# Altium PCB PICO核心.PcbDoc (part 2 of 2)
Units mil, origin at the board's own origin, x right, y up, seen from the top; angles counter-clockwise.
Board outline 3937.01 x 3543.31 mil, 4 copper layers (Top Layer, GND, VCC, Bottom Layer), stack 23.756 mil thick; 147 components, 105 nets, 477 pads, 202 vias.
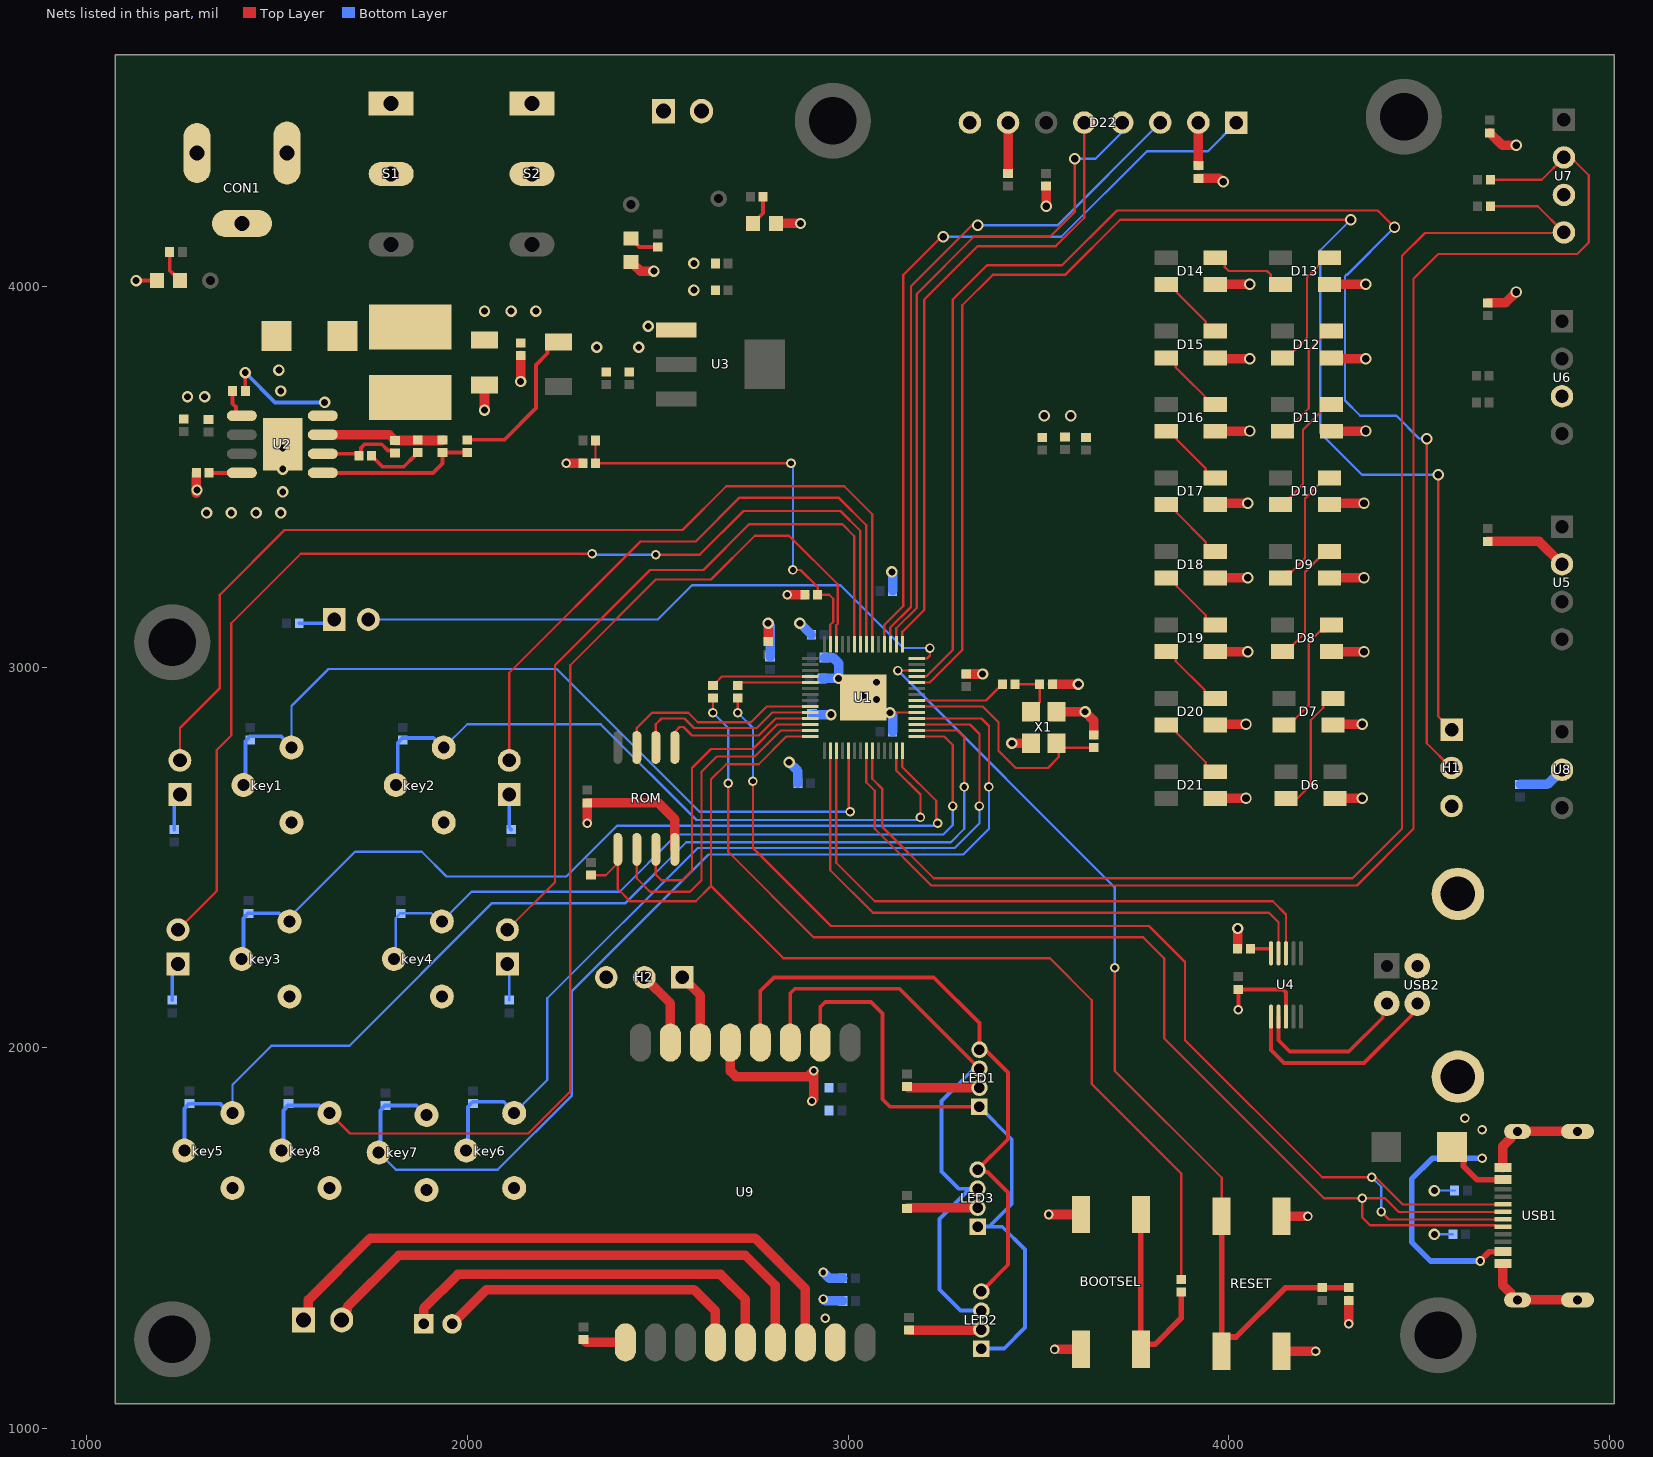
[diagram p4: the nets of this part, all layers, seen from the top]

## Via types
v1: diameter 25, hole 15, Top Layer to Bottom Layer, 71 vias
v2: diameter 30, hole 20, Top Layer to Bottom Layer, 68 vias
v3: diameter 30, hole 18, Top Layer to Bottom Layer, 63 vias

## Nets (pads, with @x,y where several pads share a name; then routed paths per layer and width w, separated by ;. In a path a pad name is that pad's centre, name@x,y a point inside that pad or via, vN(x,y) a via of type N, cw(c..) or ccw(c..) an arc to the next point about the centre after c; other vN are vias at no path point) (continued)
GND: BOOTSEL.1 C2.1 C3.1 C4.1 C5.1 C7.2 C8.1 C9.2 C10.2 C11.1 C12.2 C13.1 C14.1 C15.1 C16.1 C17.1 C18.1 C19.1 C20.1 C21.1 C22.1 C23.1 C24.1 C25.1 C26.1 C27.2 C28.1 C29.2 C30.1 C31.1 C32.1 C33.1 C34.1 C35.1 C36.1 C37.1 C38.1 C39.2 C40.2 C41.2 C42.2 CON1.2 CON1.3 D1.1 D2.2 D3.2 D4.2 D6.3 D7.3 D8.3 D9.3 D10.3 D11.3 D12.3 D13.3 D14.3 D15.3 D16.3 D17.3 D18.3 D19.3 D20.3 D21.3 D22.8 H1.3 H2.3 key1.1 key2.1 key3.1 key4.1 key5.1 key6.1 key7.1 key8.1 P1.2 R2.1 R3.1 R12.1 R13.1 R16.1 R20.2 RESET.2 ROM.4 U1.19 U1.57 U2.7 U2.9 U3.1 U4.3 U5.2 U6.3 U7.3 U8.2 U9.5 U9.16 USB1.1 USB1.12 USB1.13 USB1.14 USB1.15 USB1.16 USB2.0 USB2.4 USB2.5 X1.2 X1.4 | length 5855.8
  Top Layer w6: v3(3110,2880) 3110.63,2880.63 U1.19@3179.76,2880.63
  Top Layer w10: v3(1130,4015) D2.2@1184.37,4015 ; v1(4025,2100) C33.1@4025,2153.27 4141.73,2153.27 4150,2145 U4.3@4150,2081.93
  Top Layer w25: v3@1288.27,3456.73 C7.2@1288.27,3510 ; U2.7@1620.3,3610 1795,3610 C8.1@1810,3595 1933.27,3595 R3.1@1935,3596.73 ; v3(2045,3675) C3.1@2045,3741.34 ; v3(2140,3750) C2.1@2140,3818.27 ; v1(2260,3535) R16.1@2303.27,3535 ; v1(2315,2590) C24.1@2315,2643.27 2501.73,2643.27 2545,2600 ROM.4@2545,2521.14 ; D3.2@2430,4064.37 2430.98,4064.37 2436.79,4058.56 2436.79,4057.58 2454.37,4040 v3(2490,4040) ; U9.5@2690.64,2013.7 2690.64,1939.01 2705.28,1924.37 2894.36,1924.37 v1(2910,1940) 2910,1865 v1(2905,1860) ; C11.1@2790,3066.73 v3(2790,3115) ; D4.2@2810.31,4165 v3(2875,4165) ; v1(2840,3190) C31.1@2886.54,3190 ; C18.1@3310,2981.73 v3(3353.27,2981.73) ; v3(3430,2800) X1.4@3480,2800 ; v2(3520,4210) C35.1@3520,4263.27 ; v1(3527.16,1562.16) BOOTSEL.1@3611.26,1562.16 ; C26.1@3536.73,2955 v3(3605,2955) ; v1(3542.16,1207.84) BOOTSEL.1@3611.26,1207.84 ; X1.2@3546.93,2882.68 v3(3622.32,2882.68) 3645,2860 C25.1@3645,2821.73 ; R20.2@3920,4283.27 3975.38,4283.27 3983.65,4275 v2(3985,4275) ; D21.3@3964.47,2654.92 4044.92,2654.92 v2(4045,2655) ; D20.3@3964.47,2849.92 4044.92,2849.92 v2(4045,2850) ; D19.3@3969.47,3039.92 4049.92,3039.92 v2(4050,3040) ; D18.3@3969.47,3234.92 4049.92,3234.92 v2(4050,3235) ; D17.3@3969.47,3429.92 4049.92,3429.92 v2(4050,3430) ; D16.3@3974.47,3619.92 4054.92,3619.92 v2(4055,3620) ; D15.3@3974.47,3809.92 4054.92,3809.92 v2(4055,3810) ; D14.3@3974.47,4004.92 4054.92,4004.92 v2(4055,4005) ; C29.2@4023.27,2260 v3(4023.27,2313.27) ; RESET.2@4138.74,1202.84 v1(4227.84,1202.84) ; RESET.2@4138.74,1557.16 v1(4207.84,1557.16) ; D6.3@4269.47,2654.92 4349.92,2654.92 v2(4350,2655) ; D7.3@4269.47,2849.92 4349.92,2849.92 v2(4350,2850) ; D8.3@4274.47,3039.92 4354.92,3039.92 v2(4355,3040) ; D9.3@4274.47,3234.92 4354.92,3234.92 v2(4355,3235) ; D10.3@4274.47,3429.92 4354.92,3429.92 v2(4355,3430) ; D11.3@4279.47,3619.92 4359.92,3619.92 v2(4360,3620) ; D12.3@4279.47,3809.92 4359.92,3809.92 v2(4360,3810) ; D13.3@4279.47,4004.92 4359.92,4004.92 v2(4360,4005) ; v1(4315,1275) C27.2@4315,1336.54 ; C36.1@4680,3330 4815,3330 U5.2@4875,3270 ; C34.1@4680,3956.73 4726.73,3956.73 v2(4755,3985) ; C38.1@4685,4403.27 4718.27,4370 v2(4755,4370) ; USB1.1@4720,1433.03 4720,1376.14 4739.89,1356.25 4739.89,1344.39 4746.53,1337.76 USB1.13@4758.39,1337.76 USB1.15@4915.87,1337.76 ; USB1.12@4720,1685 4720,1741.89 4739.89,1761.78 4739.89,1773.64 4746.53,1780.28 USB1.14@4758.39,1780.28 USB1.16@4915.87,1780.28
  Bottom Layer w6: v3(4540,1510) R12.1@4588.27,1510 ; v3(4540,1625) R13.1@4593.27,1625
  Bottom Layer w25: v3(2790,3115) 2790,3113.65 2795,3108.65 C16.1@2795,3026.73 ; v3(2845,2750) 2868.27,2726.73 C12.2@2868.27,2695 ; v3(2873.27,3115) C13.1@2903.27,3085 ; C10.2@2906.73,2875 v3(2955,2875) ; C14.1@2931.73,2970 v3(2975,2970) 2975,3010.36 2960.36,3025 C19.1@2936.73,3025 ; v1(2935,1340) 2939.7,1335.3 2986.24,1335.3 C41.2@2986.54,1335 ; v1(2935,1410) 2949.97,1395.03 C39.2@2985.65,1395.03 ; v3(3110,2880) 3116.73,2873.27 C15.1@3116.73,2830 ; C17.1@3116.73,3200 v3@3116.73,3241.73 ; C9.2@3310,2981.73 v3(3353.27,2981.73) ; C37.1@4765,2691.73 4836.73,2691.73 U8.2@4875,2730
  other v1: 2940,1290
  other v2: 3515,3660 3585,3660
  other v3: 3075,2915 3040,2925 3075,2960 3115,3250 1315,3405 1380,3405 1445,3405 1510,3405 1515,3460 1290,3465 1515,3520 1515,3575 1265,3710 1310,3710 1510,3725 1505,3780 2340,3840 2450,3840 2475,3895 2595,3990 2595,4060
KEY1: key1.2 R27.1 U1.5 | length 2182.4
  Top Layer w6: U1.5@3000.63,2780.24 3001.57,2779.3 3001.57,2625.31 3000.63,2624.37 v1(3005,2620)
  Bottom Layer w6: key1.2@1537.99,2788.43 1537.99,2793.43 1537.99,2897.99 1635,2995 2235,2995 2610,2620 v1(3005,2620)
  Bottom Layer w10: key1.2@1417.01,2695 1417.01,2805.28 1422.2,2810.47 1422.2,2811.46 1429.02,2818.27 1510.64,2818.27 1535.48,2793.43 key1.2@1537.99,2793.43
KEY2: key2.2 R28.1 U1.13 | length 1833.4
  Top Layer w6: U1.13@3126.61,2780.24 3126.61,2728.39 3190,2665 v1(3190,2605)
  Bottom Layer w6: key2.2@1937.99,2788.43 1999.57,2850 2350,2850 2601.5,2598.5 3178.36,2598.5 3184.86,2605 v1(3190,2605)
  Bottom Layer w10: key2.2@1817.01,2690 1817.01,2800.28 1822.2,2805.47 1822.2,2806.46 1829.02,2813.27 1910.64,2813.27 1935.48,2788.43 key2.2@1937.99,2788.43
KEY3: key3.2 R29.1 U1.14 | length 2342.3
  Top Layer w6: U1.14@3142.36,2780.24 3142.36,2737.64 3231.36,2648.64 3231.36,2611.5 3231.36,2593.64 v1(3235,2590)
  Bottom Layer w6: key3.2@1532.99,2331.85 1532.99,2342.99 1705,2515 1880,2515 1945,2450 2260,2450 2393.5,2583.5 3223.36,2583.5 3229.86,2590 v1(3235,2590)
  Bottom Layer w10: key3.2@1412.01,2230 1412.01,2340.28 1417.2,2345.47 1417.2,2346.46 1424.02,2353.27 R29.1@1425,2353.27 1505.64,2353.27 key3.2@1530.02,2328.88
KEY4: key4.2 R30.1 U1.15 | length 2014
  Top Layer w6: U1.15@3179.76,2817.64 3252.36,2817.64 3275,2795 v1(3275,2635)
  Bottom Layer w6: key4.2@1812.01,2230 1812.01,2340.28 1817.2,2345.47 1817.2,2346.46 1824.02,2353.27 R30.1@1825,2353.27 1905.64,2353.27 1930.48,2328.43 key4.2@1937.99,2328.43 ; key4.2@1932.99,2331.85 2011.14,2410 2400,2410 2550,2560 3250,2560 3275,2585 v1(3275,2635)
KEY5: key5.2 R31.1 U1.16 | length 2900.3
  Top Layer w6: U1.16@3179.76,2833.39 3286.61,2833.39 3305,2815 v1(3305,2685)
  Bottom Layer w6: key5.2@1382.99,1828.42 1382.99,1902.99 1485,2005 1690,2005 2065,2380 2415,2380 2575,2540 3270,2540 3305,2575 v1(3305,2685)
  Bottom Layer w10: key5.2@1257.01,1730 1257.01,1840.28 1262.2,1845.47 1262.2,1846.46 1269.02,1853.27 R31.1@1270,1853.27 1350.64,1853.27 1375.48,1828.42 key5.2@1382.99,1828.42
KEY6: key6.2 R32.1 U1.17 | length 2325.4
  Top Layer w6: U1.17@3179.76,2849.13 3320,2849.13 3345,2824.13 v1(3345,2635)
  Bottom Layer w6: key6.2@2122.99,1828.42 2127.99,1833.42 2210,1915.43 2210,2130 2605,2525 3280,2525 3345,2590 v1(3345,2635)
  Bottom Layer w10: key6.2@2002.01,1735 2002.01,1845.28 2007.2,1850.47 2007.2,1851.46 2014.02,1858.27 2095.64,1858.27 2120.48,1833.42 key6.2@2127.99,1833.42
KEY7: key7.2 R33.1 U1.18 | length 2874.1
  Top Layer w6: U1.18@3179.76,2864.88 3350.12,2864.88 3370,2845 v1(3370,2685)
  Bottom Layer w6: key7.2@1767.01,1725 1812.01,1680 2080,1680 2274.53,1874.53 2274.53,2149.01 2633.01,2507.5 3302.5,2507.5 3370,2575 v1(3370,2685)
  Bottom Layer w10: key7.2@1772.01,1725 1772.01,1835.28 1777.2,1840.47 1777.2,1841.46 1784.02,1848.27 R33.1@1785,1848.27 1865.64,1848.27 1890.48,1823.42 key7.2@1892.99,1823.42 key7.2@1897.99,1823.42
KEY8: key8.2 R34.1 U1.40 | length 3127.7
  Top Layer w6: key8.2@1637.99,1828.42 1691.42,1775 2160,1775 2270,1885 2270,3005 2495,3230 2640,3230 2755,3345 2845,3345 2972.73,3217.27 2972.73,3113.36 2969.13,3109.76 U1.40@2969.13,3059.76
  Bottom Layer w10: key8.2@1517.01,1725 1517.01,1835.28 1522.2,1840.47 1522.2,1841.46 1529.02,1848.27 1610.64,1848.27 1635.48,1823.42 key8.2@1642.99,1823.42
LED1: D23.2 U1.34 | length 2682.4
  Top Layer w6: D23.2@1245,2754.88 1245,2840 1350,2945 1350,3190 1520,3360 2565,3360 2680,3475 2990,3475 3063.62,3401.38 U1.34@3063.62,3059.76
LED2: D24.2 U1.35 | length 1701.1
  Top Layer w6: D24.2@2110,2754.88 2110,2985 2455,3330 2600,3330 2715,3445 2975,3445 3047.87,3372.13 U1.35@3047.87,3059.76
LED3: D25.2 U1.36 | length 2959.1
  Top Layer w6: D25.2@1240,2310 1342,2412 1342,2782 1380,2820 1380,3115 1562.5,3297.5 v1(2327.5,3297.5) ; v1(2495,3295) 2610,3295 2725,3410 2980,3410 3032.13,3357.87 U1.36@3032.13,3059.76
  Bottom Layer w6: v1(2327.5,3297.5) 2330,3295 v1(2495,3295)
LED4: D26.2 U1.37 | length 1983.3
  Top Layer w6: D26.2@2105,2310 2230,2435 2230,3005 2480,3255 2620,3255 2740,3375 2985,3375 3016.38,3343.62 U1.37@3016.38,3059.76
LED5: D27.2 U1.28 | length 1639
  Top Layer w6: U1.28@3179.76,3022.36 3207.36,3022.36 3215,3030 v1(3215,3050)
  Bottom Layer w6: D27.2@1740,3125 2500,3125 2590,3215 2980,3215 3145,3050 v1(3215,3050)
MC+: MIC.1 U9.13 | length 1062.9
  Top Layer w25: MIC.1@1885,1275 1885,1315 1975,1405 2665,1405 2730.01,1339.99 U9.13@2730.01,1226.3
MC-: MIC.2 U9.12 | length 834.5
  Top Layer w25: MIC.2@1959.8,1275 1960,1275 2050,1365 2595,1365 2651.28,1308.72 U9.12@2651.28,1226.3
NetBOOTSEL1_2: BOOTSEL.2 R10.1 | length 562.9
  Top Layer w15: BOOTSEL.2@3768.74,1562.16 BOOTSEL.2@3768.74,1207.84 3781.98,1221.08 3806.08,1221.08 3875,1290 R10.1@3875,1358.27
NetC1_1: C1.1 D1.2 L1.1 U2.8 | length 289
  Top Layer w10: C1.1@1416.73,3725 v3(1416.73,3773.27)
  Bottom Layer w10: v3(1416.73,3773.27) 1495,3695 v3(1625,3695)
NetC1_2: C1.2 U2.1 | length 79.5
  Top Layer w10: C1.2@1383.27,3725 1383.27,3691.73 1392.08,3682.92 1392.08,3668.11 1400.19,3660 U2.1@1407.7,3660
NetC2_2: C2.2 C3.2 F1.1 L1.2 R1.2 | length 420.2
  Top Layer w10: R1.2@2000,3596.73 2096.73,3596.73 2180,3680 2180,3793.66 2210.55,3824.22 2210.55,3836.42 2227.8,3853.66 F1.1@2240,3853.66
  other v3: 2045,3935 2115,3935 2180,3935
NetC6_1: C6.1 R2.2 | length 150.1
  Top Layer w10: C6.1@1748.46,3555 1748.46,3554.02 1755.28,3547.2 1756.26,3547.2 1777.46,3526 1832.73,3526 1862.2,3555.47 1862.2,3556.46 1869.02,3563.27 R2.2@1870,3563.27
NetC6_2: C6.2 C8.2 U2.6 | length 222.7
  Top Layer w10: U2.6@1620.3,3560 1710,3560 C6.2@1715,3555 1720.41,3560.41 1720.41,3575.41 1730,3585 1775,3585 1791.65,3568.35 1803.19,3568.35 C8.2@1810,3561.54
NetC7_1: C7.1 U2.4 | length 86
  Top Layer w10: C7.1@1321.73,3510 U2.4@1407.7,3510
NetC25_2: C25.2 U1.20 X1.1 | length 627.3
  Top Layer w6: U1.20@3179.76,2896.38 3353.62,2896.38 3395,2855 3395,2780 3440,2735 3525,2735 3553.46,2763.46 3553.46,2798.66 3563.86,2788.27 C25.2@3645,2788.27
NetC26_2: C26.2 R11.1 X1.3 | length 146.8
  Top Layer w6: R11.1@3438.46,2955 C26.2@3503.27,2955 3503.27,2907.91 3480,2884.65 X1.3@3480,2882.68
NetC29_1: C29.1 U4.10 | length 65.5
  Top Layer w10: C29.1@4056.73,2260 4110.16,2260 4110.63,2259.53 U4.10@4110.63,2248.07
NetCON1_1: CON1.1 S1.1 S1.2
NetD2_1: D2.1 R4.1 | length 86.6
  Top Layer w10: R4.1@1218.27,4090 1218.27,4041.73 1230.71,4029.29 1231.69,4029.29 1245,4015.98 D2.1@1245,4015
NetD3_1: D3.1 R5.1 | length 79.6
  Top Layer w10: D3.1@2430,4125 2430.98,4125 2444.29,4111.69 2444.29,4110.71 2451.73,4103.27 R5.1@2500,4103.27
NetD4_1: D4.1 R6.1 | length 81.8
  Top Layer w10: D4.1@2749.68,4165 2749.68,4165.98 2762.99,4179.29 2763.98,4179.29 2776.73,4192.05 R6.1@2776.73,4235
NetD6_2: D6.2 D7.4 | length 337.3
  Top Layer w6: D6.2@4150,2654.92 4179.92,2654.92 4215,2690 4215,2860 4248.02,2893.02 4248.02,2901.24 4264.64,2917.86 D7.4@4273.94,2917.86
NetD7_2: D7.2 D8.4 | length 330
  Top Layer w6: D7.2@4145,2847.78 4161.63,2864.41 4174.41,2864.41 4210,2900 4210,3065 4239.1,3094.1 4252.84,3094.1 D8.4@4269.47,3110.73
NetD8_2: D8.2 D9.4 | length 326.5
  Top Layer w6: D8.2@4140.53,3040.65 4157.16,3057.27 4167.27,3057.27 4200,3090 4200,3249.91 4253.68,3303.59 D9.4@4264.47,3303.59
NetD9_2: D9.2 D10.4 | length 330.3
  Top Layer w6: D9.2@4135.53,3233.51 4152.16,3250.14 4165.14,3250.14 4200,3285 4200,3442.77 4237.06,3479.82 4239.36,3479.82 4255.98,3496.45 D10.4@4264.47,3496.45
NetD10_2: D10.2 D11.4 | length 329.7
  Top Layer w6: D10.2@4135.53,3426.37 4146.32,3426.37 4162.94,3443 4162.94,3447.94 4195,3480 4195,3623.33 4260.98,3689.31 D11.4@4269.47,3689.31
NetD11_2: D11.2 D12.4 | length 326.4
  Top Layer w6: D11.2@4140.53,3619.24 4156.56,3635.27 4165.27,3635.27 4210,3680 4210,3831.19 4260.98,3882.18 D12.4@4269.47,3882.18
NetD12_2: D12.2 D13.4 | length 326
  Top Layer w6: D12.2@4140.53,3812.1 4154.86,3826.43 4166.43,3826.43 4205,3865 4205,4024.06 4255.98,4075.04 D13.4@4264.47,4075.04
NetD13_2: D13.2 D14.4 | length 210
  Top Layer w6: D14.4@3964.47,4075.04 3972.95,4075.04 3989.58,4058.41 3989.58,4049.93 3999.51,4040 4100.49,4040 4110.42,4030.07 4110.42,4021.59 4127.05,4004.96 D13.2@4135.53,4004.96
NetD14_2: D14.2 D15.4 | length 187.5
  Top Layer w6: D14.2@3835.53,4004.96 3846.32,4004.96 3862.94,3988.33 3862.94,3983.7 3939.36,3907.29 3939.36,3898.8 3955.98,3882.18 D15.4@3964.47,3882.18
NetD15_2: D15.2 D16.4 | length 185.3
  Top Layer w6: D15.2@3835.53,3812.1 3844.02,3812.1 3860.64,3795.47 3860.64,3786.99 3958.91,3688.72 3963.88,3688.72 D16.4@3964.47,3689.31
NetD16_2: D16.2 D17.4 | length 187.5
  Top Layer w6: D16.2@3835.53,3619.24 3846.32,3619.24 3862.94,3602.61 3862.94,3597.98 3939.36,3521.56 3939.36,3513.08 3955.98,3496.45 D17.4@3964.47,3496.45
NetD17_2: D17.2 D18.4 | length 187.5
  Top Layer w6: D17.2@3835.53,3426.37 3846.32,3426.37 3862.94,3409.75 3862.94,3405.11 3939.36,3328.7 3939.36,3320.21 3955.98,3303.59 D18.4@3964.47,3303.59
NetD18_2: D18.2 D19.4 | length 187.5
  Top Layer w6: D18.2@3835.53,3233.51 3846.32,3233.51 3862.94,3216.88 3862.94,3212.25 3939.36,3135.84 3939.36,3127.35 3955.98,3110.73 D19.4@3964.47,3110.73
NetD19_2: D19.2 D20.4 | length 187.5
  Top Layer w6: D19.2@3835.53,3040.65 3844.02,3040.65 3860.64,3024.02 3860.64,3015.54 3937.06,2939.12 3937.06,2934.49 3953.68,2917.86 D20.4@3964.47,2917.86
NetD20_2: D20.2 D21.4 | length 187.5
  Top Layer w6: D20.2@3835.53,2847.78 3846.32,2847.78 3862.94,2831.16 3862.94,2826.52 3939.36,2750.11 3939.36,2741.63 3955.98,2725 D21.4@3964.47,2725
NetD22_2: D22.2 R20.1 | length 113.3
  Top Layer w25: R20.1@3920,4316.73 D22.2@3920,4430
NetD22_7: D22.7 R19.1 | length 133.3
  Top Layer w25: R19.1@3420,4296.73 D22.7@3420,4430
NetD23_1: D23.1 R35.1 | length 97.9
  Bottom Layer w10: R35.1@1230,2573.46 1230,2650.12 D23.1@1245,2665.12
NetD24_1: D24.1 R36.1 | length 93.7
  Bottom Layer w10: D24.1@2110,2665.12 2110,2578.46 R36.1@2115,2573.46
NetD25_1: D25.1 R37.1 | length 101.4
  Bottom Layer w10: R37.1@1225,2125 1225,2205.24 D25.1@1240,2220.24
NetD26_1: D26.1 R38.1 | length 97.3
  Bottom Layer w6: D26.1@2105,2220.24 2110,2215.24 R38.1@2110,2125
NetD27_1: D27.1 R39.1 | length 95.9
  Bottom Layer w10: R39.1@1558.46,3115 1640.24,3115 D27.1@1650.24,3125
NetH1_1: H1.1 U1.24 | length 3807.1
  Top Layer w6: U1.24@3179.76,2959.37 3214.37,2959.37 3300,3045 3300,3950 3380,4030 3570,4030 3715,4175 v2(4320,4175) ; v2(4550,3505) 4550,2870 H1.1@4585,2835
  Bottom Layer w6: v2(4320,4175) 4240,4095 4240,3615 4350,3505 v2(4550,3505)
NetH1_2: H1.2 U1.25 | length 3977.4
  Top Layer w6: U1.25@3179.76,2975.12 3180.25,2975.6 3205.6,2975.6 3275,3045 3275,3965 3365,4055 3562,4055 3706,4199 4391,4199 v2(4435,4155) ; v2(4520,3600) 4520,2800 H1.2@4585,2735
  Bottom Layer w6: v2(4435,4155) 4310,4030 4308.51,4030 4305,4026.49 4305,3700 4345,3660 4440,3660 4499.51,3600.49 4519.51,3600.49 v2(4520,3600)
NetH2_1: H2.1 U9.6 | length 190.7
  Top Layer w25: H2.1@2565,2185 2611.89,2138.11 U9.6@2611.89,2013.7
NetH2_2: H2.2 U9.7 | length 199.5
  Top Layer w25: H2.2@2465,2185 2533.16,2116.84 U9.7@2533.16,2013.7
NetLED1_2: LED1.2 R23.1 | length 191.4
  Top Layer w25: R23.1@3155,1898.27 3158.27,1895 LED1.2@3345,1895
NetLED2_2: LED2.2 R25.1 | length 190.7
  Top Layer w10: LED2.2@3348.27,1258.27 LED2.2@3350,1260
  Top Layer w25: R25.1@3160,1258.27 LED2.2@3348.27,1258.27
NetLED3_2: LED3.2 R26.1 | length 185.7
  Top Layer w25: R26.1@3155,1578.27 3156.73,1580 LED3.2@3340,1580
NetP1_1: P1.1 S2.1 S2.2
NetR1_1: R1.1 R3.2 U2.5 | length 418.3
  Top Layer w10: U2.5@1620.3,3510 1910,3510 1935,3535 R3.2@1935,3563.27 R1.1@2000,3563.27
NetR7_1: R7.1 U1.47 | length 193.4
  Top Layer w6: R7.1@2710,2951.73 2717.64,2959.37 U1.47@2900.24,2959.37
NetR8_1: R8.1 U1.46 | length 265.5
  Top Layer w6: R8.1@2645,2951.73 2645.98,2951.73 2654.8,2960.54 2654.8,2961.53 2668.39,2975.12 U1.46@2900.24,2975.12
NetR11_2: R11.2 U1.21 | length 243.6
  Top Layer w6: U1.21@3179.76,2912.13 3362.13,2912.13 3395.2,2945.2 3396.19,2945.2 3405,2954.02 R11.2@3405,2955
NetR24_2: R24.2 U9.9 | length 112.9
  Top Layer w25: R24.2@2305,1233.27 2311.97,1226.3 U9.9@2415.05,1226.3
NetU4_1: U4.1 USB2.3 | length 560.7
  Top Layer w10: U4.1@4110.63,2081.93 4110.63,1994.37 4145,1960 4355,1960 4479.02,2084.02 4479.02,2085.19 4495,2101.17 USB2.3@4495,2116.57
NetU4_2: U4.2 USB2.2 | length 427.2
  Top Layer w10: U4.2@4130.31,2081.93 4130.31,2019.68 4160,1990 4315,1990 4404.11,2079.11 4404.11,2105.68 USB2.2@4415,2116.57
PWM3: LED1.1 LED2.1 LED3.1 U9.2 | length 1660.2
  Top Layer w10: U9.2@2926.85,2013.7 2926.85,2106.85 2940,2120 3060,2120 3090,2090 3090,1865 3110,1845 LED1.1@3345,1845
  Bottom Layer w10: LED1.1@3345,1845 3430,1760 3430,1590 3370.8,1530.8 3340.8,1530.8 LED3.1@3340,1530 3405,1530 3465,1470 3465,1265 3410,1210 LED2.1@3350,1210
PWM4: LED1.3 LED2.3 LED3.3 U9.3 | length 1583
  Top Layer w10: U9.3@2848.12,2013.7 2848.12,2143.12 2860,2155 3135,2155 LED1.3@3345,1945
  Bottom Layer w10: LED3.3@3340,1630 LED3.3@3320,1630 ; LED1.3@3345,1945 3330,1945 3245,1860 3245,1675 3290,1630 LED3.3@3320,1630 ; LED2.3@3350,1310 3295,1310 3240,1365 3240,1550 LED3.3@3320,1630
PWM5: LED1.4 LED2.4 LED3.4 U9.4 | length 1627.6
  Top Layer w10: U9.4@2769.38,2013.7 2769.38,2149.38 2805,2185 3225,2185 3345,2065 LED1.4@3345,1995 3351.37,1988.63 3366.37,1988.63 3420,1935 3420,1760 LED3.4@3340,1680 3345.92,1674.08 3365.92,1674.08 3420,1620 3420,1430 LED2.4@3350,1360
QSPI_SCLK: ROM.6 U1.52 | length 499.8
  Top Layer w6: ROM.6@2495,2788.86 2495,2850 2510,2865 2570,2865 2595,2840 2760,2840 2800.63,2880.63 U1.52@2900.24,2880.63
QSPI_SD0: ROM.5 U1.53 | length 429.5
  Top Layer w6: ROM.5@2545,2788.86 2548.37,2792.23 2548.37,2833.39 2557.5,2842.51 2567.49,2842.51 2590,2820 2765,2820 2809.88,2864.88 U1.53@2900.24,2864.88
QSPI_SD1: ROM.2 U1.55 | length 888.2
  Top Layer w6: ROM.2@2445,2521.14 2445,2445 2480,2410 2585,2410 2615,2440 2615,2725 2655,2765 2755,2765 2823.39,2833.39 U1.55@2900.24,2833.39
QSPI_SD2: ROM.3 U1.54 | length 805.2
  Top Layer w6: ROM.3@2495,2521.14 2495,2455 2510,2440 2565,2440 2590,2465 2590,2735 2640,2785 2750,2785 2814.13,2849.13 U1.54@2900.24,2849.13
QSPI_SD3: ROM.7 U1.51 | length 550.4
  Top Layer w6: ROM.7@2445,2788.86 2445,2840 2485,2880 2580,2880 2605,2855 2745,2855 2786.38,2896.38 U1.51@2900.24,2896.38
QSPI_SS: R9.1 R10.2 ROM.1 U1.56 | length 3003.6
  Top Layer w6: R9.1@2325,2453.27 2363.27,2453.27 ROM.1@2395,2485 ; ROM.1@2395,2521.14 ROM.1@2395,2485 ; U1.56@2900.24,2817.64 2837.64,2817.64 2765,2745 2680,2745 2640,2705 2640,2425 ; R10.2@3875,1391.73 3875,1670 3640,1905 3640,2125 3530,2235 2830,2235 2640,2425 ; ROM.1@2395,2485 2395,2417.5 2427.5,2385 2600,2385 2640,2425
RUN: C27.1 R14.1 RESET.1 U1.26 | length 2583.4
  Top Layer w6: v1(3130.87,2990.87) U1.26@3179.76,2990.87 ; v1(3700,2210) 3700,1940 3981.26,1658.74 RESET.1@3981.26,1557.16
  Top Layer w15: RESET.1@3981.26,1202.84 RESET.1@3981.26,1224.04 ; RESET.1@3981.26,1557.16 RESET.1@3981.26,1224.04 ; C27.1@4315,1370 R14.1@4245,1370 4148.43,1370 4018.59,1240.16 3997.38,1240.16 RESET.1@3981.26,1224.04
  Bottom Layer w6: v1(3130.87,2990.87) 3700,2421.73 v1(3700,2210)
SP+: C43.1 U9.15 | length 1626.1
  Top Layer w25: C43.1@1569.9,1285 1582.72,1297.82 1582.72,1337.72 1745,1500 2755,1500 2887.5,1367.5 U9.15@2887.5,1226.3
SP-: C43.2 U9.14 | length 1403.5
  Top Layer w25: C43.2@1670,1285 1670,1296.97 1683.98,1310.95 1683.98,1318.98 1820,1455 2730,1455 2808.75,1376.25 U9.14@2808.75,1226.3
SPI_CLK: D22.5 U1.29 | length 1688.2
  Top Layer w6: U1.29@3142.36,3059.76 3142.36,3092.36 3200,3150 3200,3965 3340,4105 3545,4105 3620,4180 D22.5@3620,4430
SPI_DC: D22.3 U1.31 | length 1795.8
  Top Layer w6: U1.31@3110.87,3059.76 3110.87,3103.9 3165,3158.03 3165,4000 3325,4160 v2(3340,4160)
  Bottom Layer w6: v2(3340,4160) 3550,4160 D22.3@3820,4430
SPI_MISO: D22.4 U1.30 | length 1765.4
  Top Layer w6: U1.30@3126.61,3059.76 3126.61,3101.61 3180,3155 3180,3980 3330,4130 3530,4130 3595,4195 v2(3595,4335)
  Bottom Layer w6: v2(3595,4335) 3650,4335 3720,4405 D22.4@3720,4430
SPI_RST: D22.1 U1.32 | length 2033.7
  Top Layer w6: U1.32@3095.12,3059.76 3095.12,3110.12 3145,3160 3145,4030 v2@3250,4135
  Bottom Layer w6: v2(3250,4130) 3560,4130 3785,4355 3945,4355 D22.1@4020,4430
ttl_rx: U1.3 U4.8 | length 1633.4
  Top Layer w6: U1.3@2969.13,2780.24 2969.13,2485.87 3070,2385 4115,2385 4150,2350 U4.8@4150,2248.07
ttl_tx: U1.2 U4.9 | length 1628.9
  Top Layer w6: U1.2@2953.39,2780.24 2953.39,2466.61 3065,2355 4105,2355 4130.31,2329.68 U4.9@4130.31,2248.07
USB_D+: R7.2 USB1.6 USB1.8 | length 3316.8
  Top Layer w6: v1(2710,2880) R7.2@2710,2918.27 ; v1(2750,2700) 2750,2525 2955,2320 3790,2320 3885,2225 3885,2020 4245,1660 v1(4375,1660) 4385,1660 4456.46,1588.54 USB1.8@4720,1588.54 ; v1(4400,1570) 4420.83,1549.17 USB1.6@4720,1549.17
  Bottom Layer w6: v1(2710,2880) 2750,2840 v1(2750,2700) ; v1(4375,1660) 4400,1635 v1(4400,1570)
USB_D-: R8.2 USB1.5 USB1.7 | length 3400.3
  Top Layer w6: v1(2645,2880) R8.2@2645,2918.27 ; v1(2685,2695) 2685,2515 2910,2290 3775,2290 3830,2235 3830,2025 4250,1605 v1(4350,1605) ; USB1.5@4720,1529.49 4703.27,1529.49 4698.76,1534 4371,1534 4350,1555 v1(4350,1605) ; USB1.7@4720,1568.86 4446.14,1568.86 4410,1605 v1(4350,1605)
  Bottom Layer w6: v1(2645,2880) 2685,2840 v1(2685,2695)
V_SCL: R21.1 U1.9 U7.4 | length 3863
  Top Layer w6: U1.9@3063.62,2780.24 3063.62,2706.38 3090,2680 3090,2580 3225,2445 4325,2445 4455,2575 4455,4080 4515,4140 4878.43,4140 U7.4@4880,4141.57 4811.57,4210 R21.1@4686.73,4210
V_SDA: R22.1 U1.8 U7.2 | length 4171.8
  Top Layer w6: U1.8@3047.87,2780.24 3047.87,2697.13 3070,2675 3070,2575 3218.5,2426.5 4336.5,2426.5 4485,2575 4485,4020 4550,4085 4915,4085 4945,4115 4945,4291.71 4908.44,4328.27 4904.51,4328.27 4898.29,4334.49 U7.2@4898.29,4338.43 ; R22.1@4695.54,4288.81 R22.1@4686.73,4280 4821.57,4280 U7.2@4880,4338.43
Vsys: C31.2 R15.1 R16.2 U1.41 | length 1126.6
  Top Layer w6: R15.1@2336.73,3595 R16.2@2336.73,3535 v1(2850,3535) ; v1(2855,3255) 2875,3255 2920,3210 C31.2@2920,3190 ; C31.2@2920,3189.66 2950.34,3189.66 2960.73,3179.27 2960.73,3118.33 2953.39,3110.98 U1.41@2953.39,3059.76
  Bottom Layer w6: v1(2850,3535) 2850,3529.86 2855,3524.86 v1(2855,3255)
VUSBC: D5.2 USB1.2 USB1.11 | length 825.5
  Top Layer w15: D5.2@4586.62,1740 4616.09,1710.53 4616.09,1688.91 4651.5,1653.5 USB1.11@4720,1653.5 ; v1(4660,1440) 4684.13,1464.13 4719.6,1464.13 USB1.2@4720,1464.53
  Bottom Layer w15: v1(4660,1440) 4530,1440 4480,1490 4480,1655 4535,1710 v1(4665,1710)
  other v1: 4665,1785 4620,1815
pads on no net: D21.2 U2.3 U4.4 U4.5 U4.6 USB1.3 USB1.9 USB2.1

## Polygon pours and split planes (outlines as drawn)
GND on GND (split plane): 4991.91,1085.1 1095.1,1085.1 1095.1,4588.21 4991.91,4588.21
GND on VCC (split plane): 4991.91,1085.1 1095.1,1085.1 1095.1,4588.21 4991.91,4588.21
3V3 on VCC (split plane): 4914.93,1950 4914.93,1855.07 4705,1855.07 4702.06,1854.78 4699.23,1853.93 4696.63,1852.53 4694.34,1850.66 4692.47,1848.37 4691.07,1845.77 4690.22,1842.94 4689.93,1840 4689.93,1275 4690.22,1272.06 4691.07,1269.23 4692.47,1266.63 4694.34,1264.34 4696.63,1262.47 4699.23,1261.07 4702.06,1260.22 4705,1259.93 4919.93,1259.93 4919.93,1175.82 1180.82,1175.82 1180.82,4489.18 4914.93,4489.18
5V on VCC (split plane): 4114.92,2605.08 3715.08,2605.08 3715.08,3445 3714.77,3448.92 3713.85,3452.75 3712.34,3456.38 3710.29,3459.74 3707.73,3462.73 3704.74,3465.29 3701.38,3467.34 3697.75,3468.85 3693.92,3469.77 3690,3470.08 2200.08,3470.08 2200.08,3699.92 3655,3699.92 3658.92,3700.23 3662.75,3701.15 3666.38,3702.66 3669.74,3704.71 3672.73,3707.27 3675.29,3710.26 3677.34,3713.62 3678.85,3717.25 3679.77,3721.08 3680.08,3725 3680.08,4104.92 4114.92,4104.92

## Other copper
Top Layer:
  rectangle net GND: 3475,3590 3650,3665
  rectangle net 5V: 3475,3505 3650,3580
  rectangle net GND: 2895,1775 2960,1955
  rectangle net 3V3: 2980,1780 3045,2060
  rectangle net GND: 2935,1175 2995,1430
  rectangle net 5V: 3015,1175 3105,1430
  rectangle net VUSBC: 4545,1690 4685,1830
  rectangle net 5V: 4355,1695 4500,1875
  rectangle net 3V3: 2675,3730 2820,4090
  rectangle net GND: 2570,3840 2660,4090
  rectangle net GND: 2450,3840 2610,3920
  rectangle net GND: 2330,3765 2470,3920
  rectangle net 5V: 2205,3645 2605,3755
  rectangle net NetP1_1: 2030,4250 2550,4535
  rectangle net NetC2_2: 1740,3840 2295,3960
  rectangle net NetC1_1: 1660,3640 1960,3800
  rectangle net NetC1_1: 1585,3640 1715,3940
  rectangle net GND: 1520,3590 1660,3625
  rectangle net GND: 1240,3640 1335,3765
  rectangle net GND: 1275,3380 1500,3470
  rectangle net GND: 1465,3380 1570,3945
  rectangle net 12V: 1645,3985 1930,4170
  rectangle net 12V: 1295,3975 1930,4085
  rectangle net 12V: 1295,3855 1390,4070
  rectangle net 12V: 1145,3845 1390,3935
  rectangle net 12V: 1145,3550 1230,3935
  rectangle net 12V: 1160,3550 1350,3630
  rectangle net NetCON1_1: 1480,4230 1935,4550
Bottom Layer:
  rectangle net 3V3: 2675,3730 2820,4090
  rectangle net VUSBC: 4545,1690 4685,1830
  rectangle net 5V: 4355,1695 4500,1875
  rectangle net NetC2_2: 1740,3840 2295,3960
  rectangle net GND: 2895,1780 2960,2040
  rectangle net 3V3: 2975,1780 3035,2040
  rectangle net 5V: 2205,3645 2605,3755
VCC (plane layer: these items are gaps in the copper):
  lines w30: 4930,4505 4930,1950 4930,1840 4705,1840 4705,1275 4715,1275 4935,1275 4935,1160
  lines w31.5: 4930,4505 1165,4505 1165,1160 4885,1160 4935,1160
  lines w50: 2175,3720 2175,3445 3660,3445 3690,3445 3690,2580 4140,2580 4140,4130 3655,4130 3655,3725 2185,3725

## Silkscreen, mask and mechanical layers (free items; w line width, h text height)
Top Overlay:
  lines w31.5: 1135,1415 1125,1405 1125,1105 3510,1105 ; 1320,3305 2225,3305 ; 1335,3305 1125,3305 ; 2225,2365 3510,2365 3510,1105 ; 3080,4520 3080,4570 ; 3080,4555 3080,3305 ; 3095,4215 4445,4215 4445,2540 ; 3490,2365 3700,2365 3700,2540 ; 4970,1285 4970,1105 3510,1105 ; 4975,1870 4975,2550 ; 1125,3305 1125,4570 3080,4570 ; 1125,3305 1125,1410 2225,1410 2225,3305 ; 2225,3305 3080,3305 ; 3080,3305 3655,3305 3655,2900 3700,2900 3700,2540 ; 3080,4570 4975,4570 4975,2540 4710,2540 4445,2540 ; 3700,2540 4445,2540
  text "5V" at 2720,4420 h80
  text "LCD" at 4090,4395 h60
  text "-" at 2650,4265 h80
  text "SENSOR_SYS" at 4075,4265 h80
  text "+" at 2465,4255 h80
  text "LED_BOB" at 3145,3790 h80
  text "POWER" at 2590,3360 h80
  text "车内灯" at 1625,3220 h60
  text "CAR_SYS" at 1200,3210 h80
  text "CORE" at 2300,3165 h80
  text "SWD" at 4485,2945 h60
  text "车门1" at 1480,2895 h60
  text "车门2" at 1880,2895 h60
  text "车门灯1" at 1180,2540 h60
  text "车门灯2" at 2030,2535 h60
  text "AI_SYS" at 3220,2270 h80
  text "程序下载接口" at 2685,2145 h80
  text "车门灯3" at 1185,2090 h60
  text "CORE_FUN" at 3555,2080 h80
  text "车门灯4" at 1995,2015 h60
  text "车门3" at 1400,1990 h60
  text "车门4" at 1800,1985 h60
  text "车上电" at 2010,1480 h60
  text "车钥匙开门" at 1150,1470 h60
  text "锁止器" at 1475,1470 h60
  text "车顶灯开关" at 1675,1470 h60
  text "喇叭" at 1350,1315 h60
Bottom Overlay:
  drawing of 7841 lines, arcs and shapes, not listed
  text "GND" at 3355,4510 h35
  text "BL" at 3435,4510 h35
  text "VCC" at 3560,4510 h35
  text "CLK" at 3665,4510 h35
  text "MISO" at 3785,4510 h35
  text "DC" at 3860,4510 h35
  text "CS" at 3950,4510 h35
  text "RST" at 4060,4510 h35
  text "VCC" at 4965,4485 h35 r90
  text "SDA" at 4965,4375 h35 r90
  text "距离传感器" at 4790,4320 h60 r90
  text "GND" at 4965,4270 h35 r90
  text "SCL" at 4965,4165 h35 r90
  text "VCC" at 4970,3955 h35 r90
  text "温湿度传感器" at 4780,3885 h60 r90
  text "SDA" at 4970,3845 h35 r90
  text "GND" at 4970,3740 h35 r90
  text "SCL" at 4970,3635 h35 r90
  text "VCC" at 4970,3415 h35 r90
  text "PICO_MAGIX" at 3635,3385 h200
  text "GND" at 4970,3295 h35 r90
  text "气体传感器" at 4790,3250 h60 r90
  text "D" at 4970,3165 h35 r90
  text "A" at 4970,3085 h35 r90
  text "CLK" at 4530,2880 h35 r90
  text "A" at 4960,2840 h35 r90
  text "DIO" at 4530,2770 h35 r90
  text "GND" at 4960,2765 h35 r90
  text "GND" at 4530,2675 h35 r90
  text "VCC" at 4960,2655 h35 r90
  text "光强传感器" at 4795,2605 h60 r90
  text "PICO Hardware" at 3880,2040 h80
  text "Open Hardware" at 4165,1250 h80
Mechanical 13:
  lines w50: 5012.01,1347.99 5012.01,1065 1075,1065 1075,4608.31 5012.01,4608.31 5012.01,1772.01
